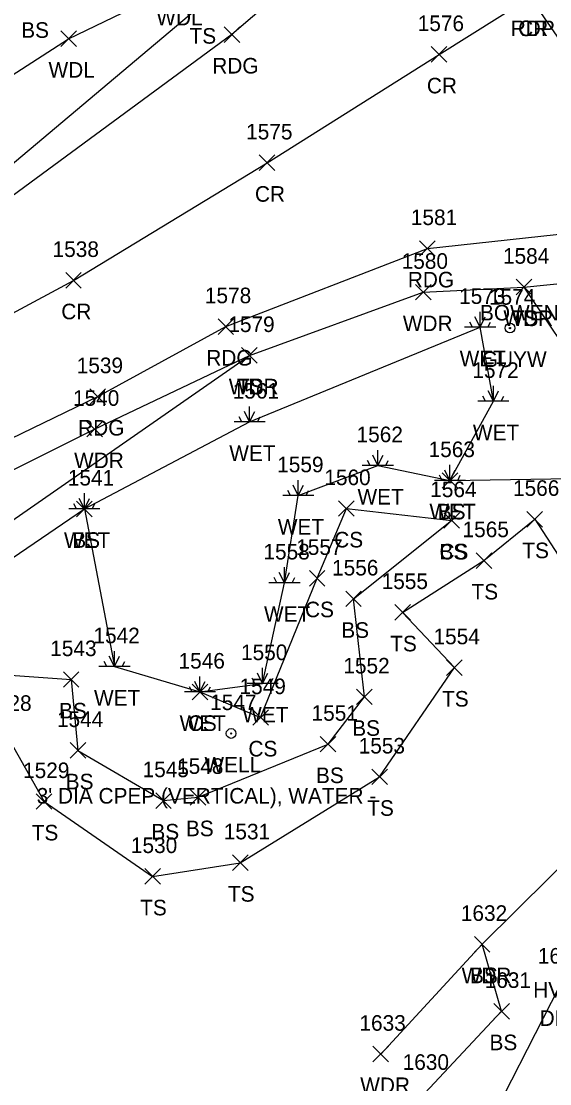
# Model space of a CAD drawing. Extents: x 1501299 to 1502485, y 381423 to 383765.
# Drawn here: x 1501589 to 1501656.9, y 383089.7 to 383226.1 of the extents above; entities that cross this region are included whole.
import ezdxf

# ---------------------------------------------------------------- set-up
doc = ezdxf.new("R2010")
doc.units = 0
for name, color, linetype in [('C_A', 7, 'Continuous'), ('L_A', 7, 'Continuous'), ('L_I', 7, 'Continuous'), ('L_TIC', 7, 'Continuous'), ('LAWA', 7, 'Continuous'), ('LELB', 7, 'Continuous'), ('LWET', 7, 'Continuous'), ('P_A', 7, 'Continuous'), ('P_I', 7, 'Continuous'), ('P_TIC', 7, 'Continuous'), ('PET', 7, 'Continuous'), ('PEU', 7, 'Continuous'), ('PRC', 7, 'Continuous'), ('R_A', 7, 'Continuous'), ('R_I', 7, 'Continuous'), ('RDG', 7, 'Continuous'), ('S_C', 7, 'Continuous'), ('U_A', 7, 'Continuous'), ('U_C', 7, 'Continuous'), ('U_I', 7, 'Continuous'), ('UPGW', 7, 'Continuous'), ('UWW', 7, 'Continuous')]:
    doc.layers.add(name, color=color, linetype=linetype)

msp = doc.modelspace()

# ---------------------------------------------------------------- linework, layer by layer
at = {"layer": 'L_TIC'}
for points in [[(1501594.13, 383222.84), (1501596.13, 383224.84)], [(1501596.13, 383222.84), (1501594.13, 383224.84)], [(1501639.68, 383190.3), (1501641.68, 383192.3)], [(1501641.68, 383190.3), (1501639.68, 383192.3)], [(1501652.61, 383190.95), (1501654.61, 383192.95)], [(1501654.61, 383190.95), (1501652.61, 383192.95)], [(1501652.61, 383190.95), (1501654.61, 383192.95)], [(1501654.61, 383190.95), (1501652.61, 383192.95)], [(1501617.34, 383182.18), (1501619.34, 383184.18)], [(1501619.34, 383182.18), (1501617.34, 383184.18)], [(1501617.34, 383182.18), (1501619.34, 383184.18)], [(1501619.34, 383182.18), (1501617.34, 383184.18)], [(1501597.46, 383172.71), (1501599.46, 383174.71)], [(1501599.46, 383172.71), (1501597.46, 383174.71)], [(1501643.1, 383166.13), (1501645.1, 383168.13)], [(1501645.1, 383166.13), (1501643.1, 383168.13)], [(1501596.16, 383162.48), (1501598.16, 383164.48)], [(1501598.16, 383162.48), (1501596.16, 383164.48)], [(1501629.8, 383162.53), (1501631.8, 383164.53)], [(1501631.8, 383162.53), (1501629.8, 383164.53)], [(1501643.31, 383160.99), (1501645.31, 383162.99)], [(1501645.31, 383160.99), (1501643.31, 383162.99)], [(1501643.31, 383160.99), (1501645.31, 383162.99)], [(1501645.31, 383160.99), (1501643.31, 383162.99)], [(1501653.99, 383161.15), (1501655.99, 383163.15)], [(1501655.99, 383161.15), (1501653.99, 383163.15)], [(1501647.46, 383155.85), (1501649.46, 383157.85)], [(1501649.46, 383155.85), (1501647.46, 383157.85)], [(1501626.05, 383153.57), (1501628.05, 383155.57)], [(1501628.05, 383153.57), (1501626.05, 383155.57)], [(1501630.71, 383150.93), (1501632.71, 383152.93)], [(1501632.71, 383150.93), (1501630.71, 383152.93)], [(1501637.02, 383149.19), (1501639.02, 383151.19)], [(1501639.02, 383149.19), (1501637.02, 383151.19)], [(1501643.68, 383142.1), (1501645.68, 383144.1)], [(1501645.68, 383142.1), (1501643.68, 383144.1)], [(1501594.46, 383140.58), (1501596.46, 383142.58)], [(1501596.46, 383140.58), (1501594.46, 383142.58)], [(1501611, 383138.98), (1501613, 383140.98)], [(1501613, 383138.98), (1501611, 383140.98)], [(1501632.11, 383138.35), (1501634.11, 383140.35)], [(1501634.11, 383138.35), (1501632.11, 383140.35)], [(1501618.78, 383135.7), (1501620.78, 383137.7)], [(1501620.78, 383135.7), (1501618.78, 383137.7)], [(1501595.32, 383131.48), (1501597.32, 383133.48)], [(1501597.32, 383131.48), (1501595.32, 383133.48)], [(1501627.45, 383132.28), (1501629.45, 383134.28)], [(1501629.45, 383132.28), (1501627.45, 383134.28)], [(1501634.07, 383128.08), (1501636.07, 383130.08)], [(1501636.07, 383128.08), (1501634.07, 383130.08)], [(1501590.98, 383124.92), (1501592.98, 383126.92)], [(1501592.98, 383124.92), (1501590.98, 383126.92)], [(1501606.32, 383125.04), (1501608.32, 383127.04)], [(1501608.32, 383125.04), (1501606.32, 383127.04)], [(1501610.75, 383125.46), (1501612.75, 383127.46)], [(1501612.75, 383125.46), (1501610.75, 383127.46)], [(1501616.18, 383117.06), (1501618.18, 383119.06)], [(1501618.18, 383117.06), (1501616.18, 383119.06)], [(1501604.91, 383115.3), (1501606.91, 383117.3)], [(1501606.91, 383115.3), (1501604.91, 383117.3)], [(1501647.24, 383106.59), (1501649.24, 383108.59)], [(1501649.24, 383106.59), (1501647.24, 383108.59)], [(1501647.24, 383106.59), (1501649.24, 383108.59)], [(1501649.24, 383106.59), (1501647.24, 383108.59)], [(1501649.74, 383097.99), (1501651.74, 383099.99)], [(1501651.74, 383097.99), (1501649.74, 383099.99)], [(1501634.22, 383092.49), (1501636.22, 383094.49)], [(1501636.22, 383092.49), (1501634.22, 383094.49)]]:
    msp.add_lwpolyline(points, dxfattribs=at)
at = {"layer": 'LAWA'}
for points in [[(1501528.63, 383177.65), (1501552.89, 383189.25), (1501565.06, 383199.71), (1501579.74, 383213.94), (1501595.13, 383223.84), (1501608.97, 383230.54), (1501610.44, 383240.69), (1501611.93, 383256.47), (1501604.57, 383266.91)], [(1501548.16, 383146.64), (1501571.52, 383160.28), (1501598.46, 383173.71), (1501618.34, 383183.18), (1501640.68, 383191.3), (1501653.61, 383191.95), (1501667.48, 383171.42), (1501677.43, 383157.35), (1501677.3, 383139.43), (1501665.74, 383124.94), (1501648.24, 383107.59), (1501635.22, 383093.49)]]:
    msp.add_lwpolyline(points, dxfattribs=at)
at = {"layer": 'LELB'}
for points in [[(1501619.16, 383281.8), (1501618.61, 383281.1), (1501625.91, 383269.99), (1501629.16, 383260.71), (1501626.95, 383253.59), (1501623.52, 383242.3), (1501612.25, 383228.2), (1501584.09, 383204.53), (1501565.56, 383192.68), (1501531.01, 383172.48)], [(1501653.61, 383191.95), (1501662.89, 383192.9), (1501675.11, 383176.66)], [(1501563.65, 383141.9), (1501573.36, 383152.56), (1501575.43, 383153.36), (1501618.34, 383183.18)], [(1501644.1, 383167.13), (1501659.65, 383167.39), (1501667.22, 383158.02), (1501673.23, 383152.87), (1501677.3, 383139.43)], [(1501568.62, 383137), (1501573.96, 383147.68), (1501597.16, 383163.48)], [(1501612, 383139.98), (1501619.78, 383136.7), (1501627.05, 383154.57), (1501630.8, 383163.53), (1501644.31, 383161.99)], [(1501574.39, 383130.88), (1501576.88, 383137.24), (1501587.12, 383134.55), (1501591.98, 383125.92), (1501605.91, 383116.3), (1501617.18, 383118.06), (1501635.07, 383129.08), (1501644.68, 383143.1), (1501638.02, 383150.19), (1501648.46, 383156.85), (1501654.99, 383162.15), (1501659.59, 383155.1), (1501663.43, 383147.57), (1501672.93, 383137.11), (1501665.74, 383124.94)], [(1501570.78, 383133.31), (1501573.28, 383143.16), (1501595.46, 383141.58), (1501596.32, 383132.48), (1501607.32, 383126.04), (1501611.75, 383126.46), (1501628.45, 383133.28), (1501633.11, 383139.35), (1501631.71, 383151.93), (1501644.31, 383161.99)], [(1501640.86, 383088.47), (1501650.74, 383098.99), (1501648.24, 383107.59)]]:
    msp.add_lwpolyline(points, dxfattribs=at)
at = {"layer": 'LWET'}
for p, q in [((1501647.98, 383186.79), (1501647.31, 383188.12)), ((1501647.98, 383186.79), (1501647.31, 383188.12)), ((1501647.98, 383186.79), (1501647.98, 383188.79)), ((1501647.98, 383186.79), (1501647.98, 383188.79)), ((1501647.98, 383186.79), (1501648.64, 383188.12)), ((1501647.98, 383186.79), (1501648.64, 383188.12)), ((1501649.98, 383186.79), (1501645.98, 383186.79)), ((1501649.98, 383186.79), (1501645.98, 383186.79)), ((1501646.98, 383186.79), (1501646.64, 383187.46)), ((1501646.98, 383186.79), (1501646.64, 383187.46)), ((1501648.98, 383186.79), (1501649.31, 383187.46)), ((1501648.98, 383186.79), (1501649.31, 383187.46)), ((1501649.68, 383177.29), (1501649.01, 383178.63)), ((1501649.68, 383177.29), (1501649.68, 383179.29)), ((1501649.68, 383177.29), (1501650.34, 383178.63)), ((1501651.68, 383177.29), (1501647.68, 383177.29)), ((1501648.68, 383177.29), (1501648.34, 383177.96)), ((1501650.68, 383177.29), (1501651.01, 383177.96)), ((1501618.38, 383174.64), (1501617.71, 383175.97)), ((1501618.38, 383174.64), (1501618.38, 383176.64)), ((1501618.38, 383174.64), (1501619.04, 383175.97)), ((1501620.38, 383174.64), (1501616.38, 383174.64)), ((1501617.38, 383174.64), (1501617.04, 383175.31)), ((1501619.38, 383174.64), (1501619.71, 383175.31)), ((1501634.85, 383169.04), (1501634.18, 383170.37)), ((1501634.85, 383169.04), (1501634.85, 383171.04)), ((1501634.85, 383169.04), (1501635.52, 383170.37)), ((1501636.85, 383169.04), (1501632.85, 383169.04)), ((1501633.85, 383169.04), (1501633.52, 383169.71)), ((1501635.85, 383169.04), (1501636.18, 383169.71)), ((1501644.1, 383167.13), (1501644.1, 383169.13)), ((1501643.1, 383167.13), (1501642.76, 383167.8)), ((1501644.1, 383167.13), (1501643.43, 383168.47)), ((1501644.1, 383167.13), (1501644.76, 383168.47)), ((1501645.1, 383167.13), (1501645.43, 383167.8)), ((1501624.62, 383165.18), (1501623.95, 383166.51)), ((1501624.62, 383165.18), (1501624.62, 383167.18)), ((1501624.62, 383165.18), (1501625.29, 383166.51)), ((1501646.1, 383167.13), (1501642.1, 383167.13)), ((1501597.16, 383163.48), (1501596.49, 383164.82)), ((1501597.16, 383163.48), (1501596.49, 383164.82)), ((1501597.16, 383163.48), (1501597.16, 383165.48)), ((1501597.16, 383163.48), (1501597.16, 383165.48)), ((1501597.16, 383163.48), (1501597.82, 383164.82)), ((1501597.16, 383163.48), (1501597.82, 383164.82)), ((1501626.62, 383165.18), (1501622.62, 383165.18)), ((1501623.62, 383165.18), (1501623.29, 383165.84)), ((1501625.62, 383165.18), (1501625.95, 383165.84)), ((1501599.16, 383163.48), (1501595.16, 383163.48)), ((1501599.16, 383163.48), (1501595.16, 383163.48)), ((1501596.16, 383163.48), (1501595.82, 383164.15)), ((1501596.16, 383163.48), (1501595.82, 383164.15)), ((1501598.16, 383163.48), (1501598.49, 383164.15)), ((1501598.16, 383163.48), (1501598.49, 383164.15)), ((1501622.85, 383153.99), (1501622.18, 383155.33)), ((1501622.85, 383153.99), (1501622.85, 383155.99)), ((1501622.85, 383153.99), (1501623.51, 383155.33)), ((1501624.85, 383153.99), (1501620.85, 383153.99)), ((1501621.85, 383153.99), (1501621.51, 383154.66)), ((1501623.85, 383153.99), (1501624.18, 383154.66)), ((1501601.02, 383143.23), (1501600.35, 383144.57)), ((1501601.02, 383143.23), (1501601.02, 383145.23)), ((1501601.02, 383143.23), (1501601.68, 383144.57)), ((1501603.02, 383143.23), (1501599.02, 383143.23)), ((1501600.02, 383143.23), (1501599.68, 383143.9)), ((1501602.02, 383143.23), (1501602.35, 383143.9)), ((1501620.05, 383141.07), (1501620.05, 383143.07)), ((1501612, 383139.98), (1501612, 383141.98)), ((1501619.05, 383141.07), (1501618.71, 383141.74)), ((1501620.05, 383141.07), (1501619.38, 383142.4)), ((1501620.05, 383141.07), (1501620.71, 383142.4)), ((1501621.05, 383141.07), (1501621.38, 383141.74)), ((1501611, 383139.98), (1501610.66, 383140.64)), ((1501612, 383139.98), (1501611.33, 383141.31)), ((1501612, 383139.98), (1501612.66, 383141.31)), ((1501613, 383139.98), (1501613.33, 383140.64)), ((1501622.05, 383141.07), (1501618.05, 383141.07)), ((1501614, 383139.98), (1501610, 383139.98))]:
    msp.add_line(p, q, dxfattribs=at)
for points in [[(1501597.16, 383163.48), (1501618.38, 383174.64), (1501647.98, 383186.79)], [(1501597.16, 383163.48), (1501601.02, 383143.23), (1501612, 383139.98), (1501620.05, 383141.07), (1501622.85, 383153.99), (1501624.62, 383165.18), (1501634.85, 383169.04), (1501644.1, 383167.13), (1501649.68, 383177.29), (1501647.98, 383186.79)]]:
    msp.add_lwpolyline(points, dxfattribs=at)
at = {"layer": 'P_TIC'}
for points in [[(1501615.1, 383223.37), (1501617.1, 383225.37)], [(1501617.1, 383223.37), (1501615.1, 383225.37)], [(1501641.7, 383220.82), (1501643.7, 383222.82)], [(1501643.7, 383220.82), (1501641.7, 383222.82)], [(1501619.62, 383206.91), (1501621.62, 383208.91)], [(1501621.62, 383206.91), (1501619.62, 383208.91)], [(1501640.2, 383195.91), (1501642.2, 383197.91)], [(1501642.2, 383195.91), (1501640.2, 383197.91)], [(1501594.76, 383191.82), (1501596.76, 383193.82)], [(1501596.76, 383191.82), (1501594.76, 383193.82)], [(1501614.32, 383185.88), (1501616.32, 383187.88)], [(1501616.32, 383185.88), (1501614.32, 383187.88)], [(1501597.87, 383176.9), (1501599.87, 383178.9)], [(1501599.87, 383176.9), (1501597.87, 383178.9)]]:
    msp.add_lwpolyline(points, dxfattribs=at)
at = {"layer": 'PET'}
msp.add_lwpolyline([(1501787.99, 383066.09), (1501768.48, 383096.75), (1501754.41, 383116.89), (1501736.24, 383144.72), (1501720.75, 383167.97), (1501712.59, 383179.72), (1501694.38, 383207.65), (1501673.6, 383237.52), (1501647.75, 383273.85), (1501633.68, 383294.63), (1501626.39, 383287.88), (1501619.16, 383281.8), (1501626.93, 383271.2), (1501654.42, 383229.17), (1501675.7, 383198.29), (1501696.7, 383166.34)], dxfattribs=at)
at = {"layer": 'PEU'}
for points in [[(1501626.93, 383271.2), (1501631.33, 383262.38), (1501631.11, 383252.37), (1501628.78, 383235.24), (1501616.1, 383224.37), (1501585.58, 383201.96), (1501565.97, 383189.42), (1501531.44, 383171.52)], [(1501544.06, 383151.18), (1501570.93, 383164.4), (1501598.87, 383177.9), (1501615.32, 383186.88), (1501641.2, 383196.91), (1501662.06, 383199.17), (1501675.7, 383198.29)]]:
    msp.add_lwpolyline(points, dxfattribs=at)
at = {"layer": 'PRC'}
msp.add_lwpolyline([(1501538.39, 383162.06), (1501572.09, 383180.11), (1501595.76, 383192.82), (1501620.62, 383207.91), (1501642.7, 383221.82), (1501654.42, 383229.17)], dxfattribs=at)
at = {"layer": 'RDG'}
msp.add_lwpolyline([(1501662.06, 383199.17), (1501675.11, 383176.66), (1501684.59, 383158.08), (1501685.54, 383149.23), (1501676.08, 383131.44), (1501669.33, 383121.4), (1501658.13, 383102.11), (1501647.9, 383082.12)], dxfattribs=at)
at = {"layer": 'UPGW'}
for radius in [0.625, 0.0833]:
    msp.add_circle((1501651.81, 383186.69), radius, dxfattribs=at)
at = {"layer": 'UWW'}
for radius in [0.625, 0.0833]:
    msp.add_circle((1501616, 383134.65), radius, dxfattribs=at)

# ---------------------------------------------------------------- texts
at = {"layer": 'C_A'}
msp.add_text('HVCTRL', height=2, dxfattribs=at).set_placement((1501654.79, 383100.75))
at = {"layer": 'L_A'}
for s, p in [('WDL', (1501606.39, 383225.54)), ('BS', (1501589.04, 383223.95)), ('TS', (1501610.66, 383223.2)), ('WDL', (1501592.55, 383218.84)), ('WDR', (1501638.05, 383186.3)), ('WDR', (1501650.97, 383186.95)), ('TS', (1501652.02, 383186.95)), ('WET', (1501645.35, 383181.79)), ('WET', (1501645.35, 383181.79)), ('WDR', (1501615.7, 383178.18)), ('TS', (1501616.75, 383178.18)), ('WET', (1501647.05, 383172.29)), ('WET', (1501615.76, 383169.64)), ('WDR', (1501595.83, 383168.71)), ('WET', (1501632.23, 383164.04)), ('WET', (1501641.47, 383162.13)), ('BS', (1501642.54, 383162.13)), ('WET', (1501622, 383160.18)), ('WET', (1501594.53, 383158.48)), ('WET', (1501594.53, 383158.48)), ('BS', (1501595.6, 383158.48)), ('CS', (1501629.24, 383158.53)), ('CS', (1501642.75, 383156.99)), ('BS', (1501642.75, 383156.99)), ('TS', (1501653.4, 383157.15)), ('TS', (1501646.87, 383151.85)), ('CS', (1501625.49, 383149.57)), ('WET', (1501620.22, 383148.99)), ('BS', (1501630.15, 383146.93)), ('TS', (1501636.43, 383145.19)), ('WET', (1501598.39, 383138.23)), ('TS', (1501643.09, 383138.1)), ('BS', (1501593.9, 383136.58)), ('WET', (1501617.42, 383136.07)), ('WET', (1501609.38, 383134.98)), ('CS', (1501610.44, 383134.98)), ('BS', (1501631.55, 383134.35)), ('CS', (1501618.22, 383131.7)), ('BS', (1501594.76, 383127.48)), ('BS', (1501626.9, 383128.28)), ('TS', (1501633.48, 383124.08)), ('TS', (1501590.39, 383120.92)), ('BS', (1501605.76, 383121.04)), ('BS', (1501610.19, 383121.46)), ('TS', (1501615.59, 383113.06)), ('TS', (1501604.32, 383111.3)), ('WDR', (1501645.6, 383102.59)), ('BS', (1501646.68, 383102.59)), ('BS', (1501649.18, 383093.99)), ('WDR', (1501632.58, 383088.49))]:
    msp.add_text(s, height=2, dxfattribs=at).set_placement(p)
at = {"layer": 'L_I'}
for s, p in [('1580', (1501637.9, 383194.3)), ('1584', (1501650.91, 383194.95)), ('1584', (1501650.91, 383194.95)), ('1573', (1501645.28, 383189.79)), ('1573', (1501645.28, 383189.79)), ('1579', (1501615.64, 383186.18)), ('1579', (1501615.64, 383186.18)), ('1572', (1501646.98, 383180.29)), ('1540', (1501595.69, 383176.71)), ('1561', (1501616.2, 383177.64)), ('1562', (1501632.11, 383172.04)), ('1563', (1501641.36, 383170.13)), ('1563', (1501641.36, 383170.13)), ('1559', (1501621.92, 383168.18)), ('1541', (1501595.03, 383166.48)), ('1541', (1501595.03, 383166.48)), ('1541', (1501595.03, 383166.48)), ('1560', (1501627.97, 383166.53)), ('1564', (1501641.57, 383164.99)), ('1564', (1501641.57, 383164.99)), ('1566', (1501652.2, 383165.15)), ('1565', (1501645.72, 383159.85)), ('1557', (1501624.36, 383157.57)), ('1558', (1501620.15, 383156.99)), ('1556', (1501628.96, 383154.93)), ('1555', (1501635.33, 383153.19)), ('1542', (1501598.32, 383146.23)), ('1554', (1501641.99, 383146.1)), ('1543', (1501592.77, 383144.58)), ('1550', (1501617.27, 383144.07)), ('1546', (1501609.25, 383142.98)), ('1546', (1501609.25, 383142.98)), ('1552', (1501630.41, 383142.35)), ('1549', (1501617.08, 383139.7)), ('1528', (1501584.43, 383137.55)), ('1544', (1501593.63, 383135.48)), ('1551', (1501626.33, 383136.28)), ('1553', (1501632.38, 383132.08)), ('1529', (1501589.28, 383128.92)), ('1545', (1501604.63, 383129.04)), ('1548', (1501609.06, 383129.46)), ('1531', (1501615.06, 383121.06)), ('1530', (1501603.13, 383119.3)), ('1632', (1501645.5, 383110.59)), ('1632', (1501645.5, 383110.59)), ('1631', (1501648.56, 383101.99)), ('1633', (1501632.48, 383096.49)), ('1630', (1501638.03, 383091.47))]:
    msp.add_text(s, height=2, dxfattribs=at).set_placement(p)
at = {"layer": 'P_A'}
for s, p in [('RDP', (1501651.91, 383224.17)), ('CR', (1501652.86, 383224.17)), ('RDG', (1501613.58, 383219.37)), ('CR', (1501641.14, 383216.82)), ('CR', (1501619.06, 383202.91)), ('RDG', (1501638.69, 383191.91)), ('CR', (1501594.19, 383187.82)), ('RDG', (1501612.81, 383181.88)), ('RDG', (1501596.35, 383172.9))]:
    msp.add_text(s, height=2, dxfattribs=at).set_placement(p)
at = {"layer": 'P_I'}
for s, p in [('1576', (1501639.96, 383224.82)), ('1575', (1501617.93, 383210.91)), ('1581', (1501639.08, 383199.91)), ('1538', (1501593.07, 383195.82)), ('1578', (1501612.63, 383189.88)), ('1539', (1501596.17, 383180.9))]:
    msp.add_text(s, height=2, dxfattribs=at).set_placement(p)
at = {"layer": 'R_A'}
msp.add_text('DRG', height=2, dxfattribs=at).set_placement((1501655.62, 383097.11))
at = {"layer": 'R_I'}
msp.add_text('1627', height=2, dxfattribs=at).set_placement((1501655.39, 383105.11))
at = {"layer": 'S_C'}
msp.add_text('BOWEN WAY PVT.', height=2, dxfattribs=at).set_placement((1501647.96, 383187.67))
at = {"layer": 'U_A'}
for s, p in [('GUYW', (1501648.2, 383181.69)), ('WELL', (1501612.57, 383129.65))]:
    msp.add_text(s, height=2, dxfattribs=at).set_placement(p)
at = {"layer": 'U_C'}
msp.add_text("3' DIA CPEP (VERTICAL), WATER -", height=2, dxfattribs=at).set_placement((1501591.03, 383125.65))
at = {"layer": 'U_I'}
for s, p in [('1574', (1501649.11, 383189.69)), ('1547', (1501613.31, 383137.65))]:
    msp.add_text(s, height=2, dxfattribs=at).set_placement(p)

doc.saveas('drawing.dxf')
